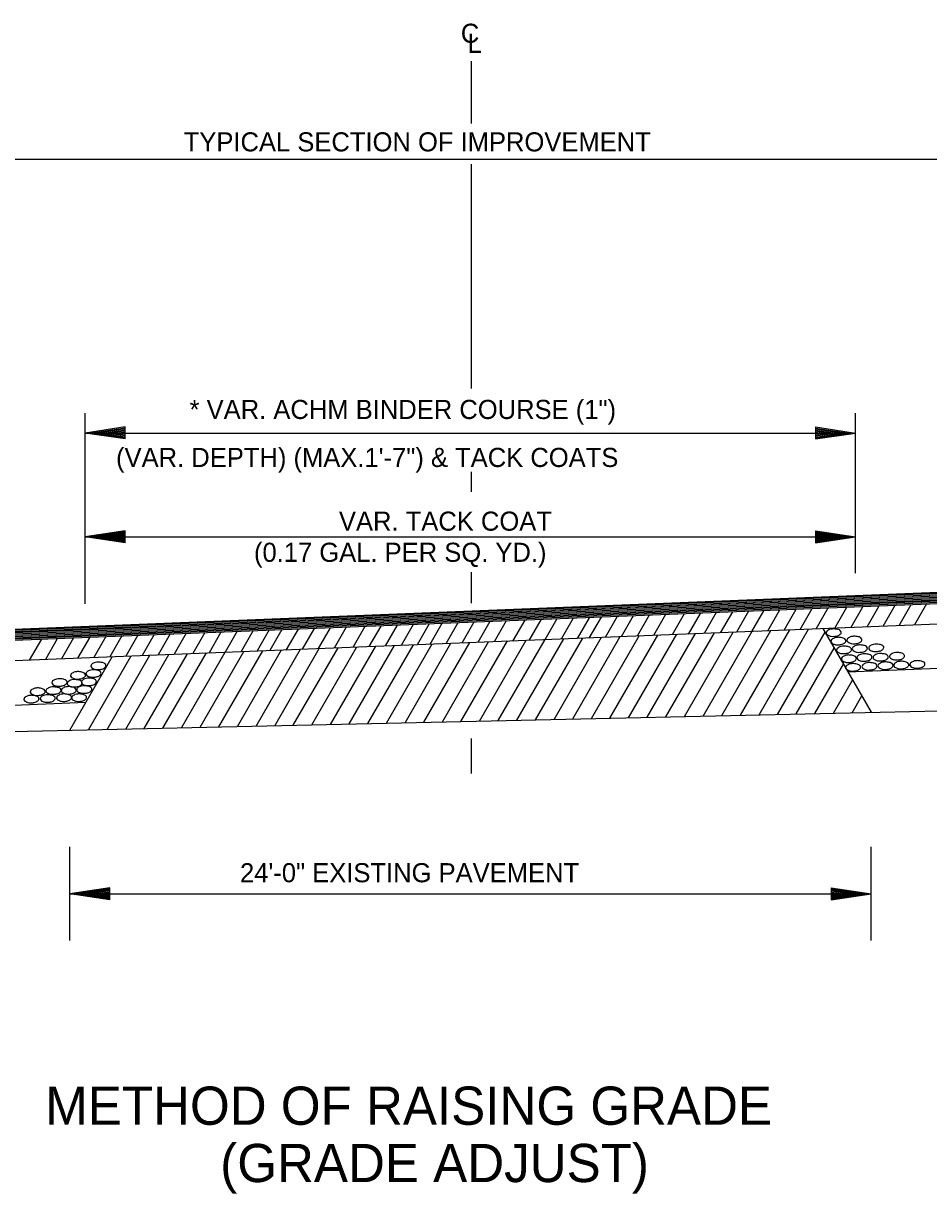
# Model space of a CAD drawing. Extents: x -2842 to 2681, y -2139 to 474.
# Drawn here: x 1630.4 to 1914.6, y -130.7 to 236.8 of the extents above; entities that cross this region are included whole.
import ezdxf

# ---------------------------------------------------------------- set-up
doc = ezdxf.new("R2010")
doc.units = 0
doc.layers.add('R_Grid', color=7, linetype='Continuous')

msp = doc.modelspace()

# ---------------------------------------------------------------- linework, layer by layer
at = {"layer": 'R_Grid'}
for p, q in [((1771.14, 205.36), (1771.14, 224.85)), ((1450.73, 194.15), (2091.8, 194.15)), ((1771.14, 129.55), (1771.14, 192.5)), ((1771.14, 122.12), (1771.14, 129.55)), ((1649.84, 54.48), (1649.84, 114.32)), ((1891.67, 64.06), (1891.67, 114.32)), ((1662.4, 110.03), (1649.84, 108.12)), ((1649.84, 108.12), (1891.67, 108.12)), ((1662.4, 106.24), (1649.84, 108.12)), ((1662.4, 109.69), (1651.92, 108.12)), ((1662.4, 106.55), (1651.92, 108.12)), ((1662.4, 109.42), (1654.08, 108.12)), ((1662.4, 106.85), (1654.08, 108.12)), ((1662.4, 109.06), (1656.19, 108.12)), ((1662.4, 107.19), (1656.19, 108.12)), ((1662.4, 108.76), (1658.31, 108.12)), ((1662.4, 107.49), (1658.31, 108.12)), ((1662.4, 108.42), (1660.42, 108.12)), ((1662.4, 107.84), (1660.42, 108.12)), ((1662.4, 106.24), (1662.4, 110.03)), ((1879.1, 110.03), (1891.67, 108.12)), ((1879.1, 110.03), (1879.1, 106.24)), ((1879.1, 109.69), (1889.56, 108.12)), ((1879.1, 109.42), (1887.39, 108.12)), ((1879.1, 109.06), (1885.28, 108.12)), ((1879.1, 108.76), (1883.15, 108.12)), ((1879.1, 108.42), (1881.09, 108.12)), ((1879.1, 106.24), (1891.67, 108.12)), ((1879.1, 107.49), (1883.15, 108.12)), ((1879.1, 106.85), (1887.39, 108.12)), ((1879.1, 106.55), (1889.56, 108.12)), ((1879.1, 107.19), (1885.28, 108.12)), ((1879.1, 107.84), (1881.09, 108.12)), ((1771.14, 89.65), (1771.14, 95.96)), ((1662.4, 77.41), (1649.84, 75.54)), ((1662.4, 73.64), (1662.4, 77.41)), ((1879.1, 77.41), (1891.67, 75.54)), ((1879.1, 77.41), (1879.1, 73.64)), ((1649.84, 75.54), (1891.67, 75.54)), ((1662.4, 73.64), (1649.84, 75.54)), ((1662.4, 77.12), (1651.92, 75.54)), ((1662.4, 73.98), (1651.92, 75.54)), ((1662.4, 76.79), (1654.08, 75.54)), ((1662.4, 74.28), (1654.08, 75.54)), ((1662.4, 76.5), (1656.19, 75.54)), ((1662.4, 74.61), (1656.19, 75.54)), ((1662.4, 76.13), (1658.31, 75.54)), ((1662.4, 74.92), (1658.31, 75.54)), ((1662.4, 75.85), (1660.42, 75.54)), ((1662.4, 75.25), (1660.42, 75.54)), ((1879.1, 77.12), (1889.56, 75.54)), ((1879.1, 76.79), (1887.39, 75.54)), ((1879.1, 76.5), (1885.28, 75.54)), ((1879.1, 76.13), (1883.15, 75.54)), ((1879.1, 75.85), (1881.09, 75.54)), ((1879.1, 73.64), (1891.67, 75.54)), ((1879.1, 74.92), (1883.15, 75.54)), ((1879.1, 74.28), (1887.39, 75.54)), ((1879.1, 73.98), (1889.56, 75.54)), ((1879.1, 74.61), (1885.28, 75.54)), ((1879.1, 75.25), (1881.09, 75.54)), ((1447.46, 37.85), (2094.71, 63.67)), ((1448.3, 38.28), (2093.98, 64.03)), ((1449.13, 38.68), (2093.27, 64.39)), ((1449.98, 39.13), (2092.52, 64.76)), ((1450.73, 39.48), (2091.83, 65.1)), ((1771.14, 54.66), (1771.14, 64.38)), ((1546.01, 40.97), (1996.02, 58.89)), ((1546.28, 41.37), (1995.73, 59.31)), ((1545.25, 39.8), (1996.79, 57.76)), ((1545.53, 40.17), (1996.53, 58.15)), ((1545.77, 40.58), (1996.27, 58.53)), ((1541.13, 33.2), (2001.08, 51.5)), ((1847.96, 51.75), (1844.19, 45.17)), ((1853.02, 51.95), (1849.24, 45.37)), ((1858.07, 52.13), (1854.29, 45.6)), ((1862.81, 52.29), (1859.03, 45.75)), ((1867.88, 52.53), (1864.08, 45.92)), ((1872.92, 52.71), (1869.15, 46.14)), ((1877.97, 52.9), (1874.19, 46.35)), ((1882.99, 53.13), (1879.24, 46.55)), ((1888.88, 53.36), (1885.08, 46.77)), ((1893.91, 53.45), (1890.18, 47)), ((1899.01, 53.76), (1895.22, 47.18)), ((1904.06, 53.97), (1900.29, 47.39)), ((1909.1, 54.15), (1905.33, 47.59)), ((1914.01, 54.44), (1910.25, 47.84)), ((1747.76, 47.8), (1743.96, 41.26)), ((1752.8, 48.01), (1749.03, 41.42)), ((1757.86, 48.21), (1754.07, 41.63)), ((1761.76, 48.29), (1757.99, 41.72)), ((1766.83, 48.47), (1763.04, 41.93)), ((1771.87, 48.68), (1768.09, 42.1)), ((1776.91, 48.91), (1773.15, 42.31)), ((1781.98, 49.1), (1778.22, 42.54)), ((1787.83, 49.31), (1784.03, 42.74)), ((1792.86, 49.42), (1789.14, 42.95)), ((1797.94, 49.74), (1794.19, 43.15)), ((1803.02, 49.92), (1799.23, 43.39)), ((1808.06, 50.12), (1804.29, 43.56)), ((1811.78, 50.31), (1807.99, 43.72)), ((1816.86, 50.52), (1813.05, 43.92)), ((1821.88, 50.68), (1818.12, 44.16)), ((1826.93, 50.89), (1823.16, 44.33)), ((1831.99, 51.13), (1828.22, 44.52)), ((1837.86, 51.32), (1834.08, 44.77)), ((1842.88, 51.42), (1839.15, 44.98)), ((1656.28, 44.2), (1652.5, 37.65)), ((1661.32, 44.43), (1657.53, 37.86)), ((1666.39, 44.63), (1662.62, 38.07)), ((1671.43, 44.88), (1667.66, 38.29)), ((1676.49, 45.05), (1672.73, 38.48)), ((1681.52, 45.25), (1677.76, 38.67)), ((1687.38, 45.5), (1683.61, 38.91)), ((1692.42, 45.6), (1688.69, 39.13)), ((1697.5, 45.88), (1693.74, 39.31)), ((1702.57, 46.09), (1698.8, 39.52)), ((1707.6, 46.31), (1703.84, 39.75)), ((1711.54, 46.36), (1707.77, 39.81)), ((1716.65, 46.56), (1712.85, 39.97)), ((1721.66, 46.75), (1717.89, 40.19)), ((1726.73, 46.97), (1722.95, 40.4)), ((1731.76, 47.17), (1728, 40.6)), ((1737.6, 47.4), (1733.82, 40.81)), ((1742.63, 47.5), (1738.91, 41.04)), ((1802.9, 18.32), (1817.85, 44.21)), ((1808.75, 18.45), (1823.76, 44.44)), ((1814.6, 18.58), (1829.67, 44.68)), ((1820.45, 18.71), (1835.58, 44.91)), ((1826.3, 18.84), (1841.49, 45.15)), ((1832.15, 18.98), (1847.4, 45.38)), ((1838, 19.11), (1853.31, 45.62)), ((1843.85, 19.24), (1859.22, 45.86)), ((1849.7, 19.37), (1865.13, 46.09)), ((1855.55, 19.5), (1871.04, 46.33)), ((1861.4, 19.63), (1876.94, 46.56)), ((1867.25, 19.76), (1882.15, 45.57)), ((1881.47, 46.74), (1896.62, 20.43)), ((1636.05, 43.4), (1632.26, 36.81)), ((1641.05, 43.49), (1637.33, 37.02)), ((1646.15, 43.77), (1642.38, 37.22)), ((1651.23, 43.99), (1647.44, 37.43)), ((1709.31, 16.21), (1723.3, 40.45)), ((1715.16, 16.34), (1729.21, 40.68)), ((1721.01, 16.48), (1735.12, 40.92)), ((1726.86, 16.61), (1741.03, 41.15)), ((1732.71, 16.74), (1746.94, 41.39)), ((1738.56, 16.87), (1752.85, 41.62)), ((1744.41, 17), (1758.76, 41.86)), ((1750.26, 17.13), (1764.67, 42.09)), ((1756.11, 17.27), (1770.58, 42.33)), ((1761.96, 17.4), (1776.49, 42.56)), ((1767.81, 17.53), (1782.4, 42.8)), ((1773.66, 17.66), (1788.31, 43.03)), ((1779.51, 17.79), (1794.21, 43.27)), ((1785.36, 17.92), (1800.12, 43.5)), ((1791.2, 18.05), (1806.03, 43.74)), ((1797.05, 18.19), (1811.94, 43.97)), ((1873.1, 19.9), (1885.03, 40.56)), ((1644.97, 14.77), (1658.27, 37.86)), ((1644.97, 14.77), (1658.3, 37.86)), ((1650.82, 14.9), (1664.21, 38.09)), ((1656.67, 15.03), (1670.12, 38.33)), ((1662.52, 15.16), (1676.03, 38.56)), ((1668.37, 15.29), (1681.94, 38.8)), ((1674.22, 15.42), (1687.85, 39.04)), ((1680.06, 15.55), (1693.76, 39.27)), ((1685.91, 15.69), (1699.67, 39.51)), ((1691.76, 15.82), (1705.58, 39.74)), ((1697.61, 15.95), (1711.48, 39.98)), ((1703.46, 16.08), (1717.39, 40.21)), ((1889.32, 33.11), (2010.36, 37.94)), ((1878.95, 20.03), (1887.91, 35.56)), ((1884.8, 20.16), (1890.79, 30.55)), ((1398.89, 13.57), (1650.04, 23.58)), ((1890.65, 20.29), (1893.68, 25.54)), ((1594.52, 13.63), (1946.93, 21.56)), ((1896.49, 20.42), (1896.56, 20.54)), ((1771.14, 1.22), (1771.14, 12.2)), ((1644.97, -51.3), (1644.97, -21.87)), ((1896.62, -51.3), (1896.62, -21.87)), ((1657.55, -34.75), (1644.97, -36.64)), ((1644.97, -36.64), (1896.62, -36.64)), ((1657.55, -38.52), (1644.97, -36.64)), ((1657.55, -35.05), (1647.06, -36.64)), ((1657.55, -38.19), (1647.06, -36.64)), ((1657.55, -35.39), (1649.25, -36.64)), ((1657.55, -37.88), (1649.25, -36.64)), ((1657.55, -35.67), (1651.32, -36.64)), ((1657.55, -37.57), (1651.32, -36.64)), ((1657.55, -36.03), (1653.47, -36.64)), ((1657.55, -37.25), (1653.47, -36.64)), ((1657.55, -36.31), (1655.56, -36.64)), ((1657.55, -36.92), (1655.56, -36.64)), ((1657.55, -38.52), (1657.55, -34.75)), ((1884.05, -34.75), (1896.62, -36.64)), ((1884.05, -34.75), (1884.05, -38.52)), ((1884.05, -35.05), (1894.5, -36.64)), ((1884.05, -35.39), (1892.35, -36.64)), ((1884.05, -35.67), (1890.27, -36.64)), ((1884.05, -36.03), (1888.14, -36.64)), ((1884.05, -36.31), (1886.01, -36.64)), ((1884.05, -38.52), (1896.62, -36.64)), ((1884.05, -37.25), (1888.14, -36.64)), ((1884.05, -37.88), (1892.35, -36.64)), ((1884.05, -38.19), (1894.5, -36.64)), ((1884.05, -37.57), (1890.27, -36.64)), ((1884.05, -36.92), (1886.01, -36.64))]:
    msp.add_line(p, q, dxfattribs=at)
for points in [[(1884.85, 44.27), (1884.01, 44.28), (1883.1, 44.61), (1882.56, 45.06), (1882.51, 45.32), (1882.72, 45.88), (1883.04, 46.11), (1883.57, 46.38), (1884.39, 46.56), (1884.78, 46.6), (1885.42, 46.55), (1886.1, 46.44), (1886.64, 46.26), (1887.14, 45.83), (1887.23, 45.54), (1887.08, 45.08), (1886.7, 44.74), (1886.32, 44.5), (1885.75, 44.36), (1885.38, 44.28), (1884.85, 44.27)], [(1891.32, 41.96), (1890.48, 41.97), (1889.57, 42.3), (1889.03, 42.75), (1888.98, 43.01), (1889.2, 43.56), (1889.51, 43.8), (1890.05, 44.07), (1890.86, 44.25), (1891.25, 44.29), (1891.89, 44.24), (1892.58, 44.13), (1893.11, 43.95), (1893.61, 43.52), (1893.7, 43.23), (1893.56, 42.76), (1893.18, 42.42), (1892.8, 42.19), (1892.22, 42.05), (1891.86, 41.97), (1891.32, 41.96)], [(1886.3, 41.63), (1885.46, 41.64), (1884.55, 41.96), (1884.01, 42.42), (1883.96, 42.68), (1884.18, 43.23), (1884.49, 43.47), (1885.03, 43.74), (1885.84, 43.92), (1886.23, 43.96), (1886.87, 43.91), (1887.56, 43.8), (1888.09, 43.61), (1888.59, 43.19), (1888.68, 42.9), (1888.54, 42.43), (1888.16, 42.09), (1887.78, 41.86), (1887.2, 41.72), (1886.84, 41.64), (1886.3, 41.63)], [(1888.09, 38.85), (1887.25, 38.87), (1886.33, 39.19), (1885.8, 39.64), (1885.74, 39.9), (1885.96, 40.46), (1886.28, 40.7), (1886.81, 40.96), (1887.63, 41.15), (1888.01, 41.19), (1888.65, 41.13), (1889.34, 41.03), (1889.87, 40.84), (1890.38, 40.41), (1890.47, 40.13), (1890.32, 39.66), (1889.94, 39.32), (1889.56, 39.09), (1888.98, 38.95), (1888.62, 38.87), (1888.09, 38.85)], [(1893.04, 39.25), (1892.2, 39.26), (1891.29, 39.59), (1890.75, 40.04), (1890.69, 40.3), (1890.91, 40.86), (1891.23, 41.09), (1891.76, 41.36), (1892.58, 41.54), (1892.97, 41.59), (1893.61, 41.53), (1894.29, 41.42), (1894.83, 41.24), (1895.33, 40.81), (1895.42, 40.53), (1895.27, 40.06), (1894.89, 39.72), (1894.51, 39.48), (1893.94, 39.34), (1893.57, 39.26), (1893.04, 39.25)], [(1898.19, 39.51), (1897.35, 39.53), (1896.44, 39.85), (1895.9, 40.3), (1895.85, 40.56), (1896.06, 41.12), (1896.38, 41.36), (1896.91, 41.62), (1897.73, 41.81), (1898.12, 41.85), (1898.76, 41.79), (1899.45, 41.69), (1899.98, 41.5), (1900.48, 41.07), (1900.57, 40.79), (1900.42, 40.32), (1900.04, 39.98), (1899.66, 39.75), (1899.09, 39.61), (1898.73, 39.53), (1898.19, 39.51)], [(1889.61, 36.08), (1888.76, 36.09), (1887.85, 36.42), (1887.32, 36.87), (1887.26, 37.13), (1887.48, 37.69), (1887.79, 37.92), (1888.33, 38.19), (1889.15, 38.37), (1889.53, 38.41), (1890.17, 38.36), (1890.86, 38.25), (1891.39, 38.07), (1891.9, 37.64), (1891.98, 37.36), (1891.84, 36.89), (1891.46, 36.55), (1891.08, 36.31), (1890.5, 36.17), (1890.14, 36.09), (1889.61, 36.08)], [(1894.49, 36.47), (1893.65, 36.49), (1892.74, 36.81), (1892.2, 37.27), (1892.15, 37.53), (1892.37, 38.08), (1892.68, 38.32), (1893.22, 38.58), (1894.03, 38.77), (1894.42, 38.81), (1895.06, 38.75), (1895.75, 38.65), (1896.28, 38.46), (1896.78, 38.03), (1896.87, 37.75), (1896.73, 37.28), (1896.35, 36.94), (1895.97, 36.71), (1895.39, 36.57), (1895.03, 36.49), (1894.49, 36.47)], [(1899.58, 36.54), (1898.74, 36.56), (1897.82, 36.88), (1897.29, 37.33), (1897.23, 37.59), (1897.45, 38.15), (1897.77, 38.38), (1898.3, 38.65), (1899.12, 38.84), (1899.51, 38.88), (1900.14, 38.82), (1900.83, 38.72), (1901.37, 38.53), (1901.87, 38.1), (1901.96, 37.82), (1901.81, 37.35), (1901.43, 37.01), (1901.05, 36.77), (1900.48, 36.64), (1900.11, 36.56), (1899.58, 36.54)], [(1904.73, 36.87), (1903.89, 36.89), (1902.97, 37.21), (1902.44, 37.66), (1902.38, 37.92), (1902.6, 38.48), (1902.92, 38.71), (1903.45, 38.98), (1904.27, 39.17), (1904.66, 39.21), (1905.3, 39.15), (1905.98, 39.05), (1906.52, 38.86), (1907.02, 38.43), (1907.11, 38.15), (1906.96, 37.68), (1906.58, 37.34), (1906.2, 37.1), (1905.63, 36.97), (1905.26, 36.89), (1904.73, 36.87)], [(1647.53, 30.85), (1646.69, 30.87), (1645.78, 31.19), (1645.25, 31.65), (1645.19, 31.91), (1645.41, 32.46), (1645.72, 32.7), (1646.26, 32.97), (1647.07, 33.15), (1647.46, 33.19), (1648.1, 33.14), (1648.79, 33.03), (1649.32, 32.84), (1649.82, 32.42), (1649.91, 32.13), (1649.77, 31.66), (1649.39, 31.32), (1649.01, 31.09), (1648.43, 30.95), (1648.07, 30.87), (1647.53, 30.85)], [(1652.41, 31.45), (1651.57, 31.47), (1650.65, 31.79), (1650.12, 32.25), (1650.06, 32.5), (1650.28, 33.06), (1650.6, 33.3), (1651.13, 33.56), (1651.95, 33.75), (1652.34, 33.79), (1652.98, 33.73), (1653.66, 33.63), (1654.2, 33.44), (1654.7, 33.01), (1654.79, 32.73), (1654.64, 32.26), (1654.26, 31.92), (1653.88, 31.69), (1653.31, 31.55), (1652.94, 31.47), (1652.41, 31.45)], [(1653.95, 33.85), (1653.11, 33.86), (1652.19, 34.19), (1651.66, 34.64), (1651.6, 34.9), (1651.82, 35.46), (1652.14, 35.69), (1652.67, 35.96), (1653.49, 36.14), (1653.88, 36.19), (1654.52, 36.13), (1655.2, 36.02), (1655.74, 35.84), (1656.24, 35.41), (1656.33, 35.13), (1656.18, 34.66), (1655.8, 34.32), (1655.42, 34.08), (1654.85, 33.94), (1654.48, 33.86), (1653.95, 33.85)], [(1890.93, 33.37), (1890.09, 33.39), (1889.17, 33.71), (1888.64, 34.16), (1888.58, 34.42), (1888.8, 34.98), (1889.12, 35.21), (1889.65, 35.48), (1890.47, 35.67), (1890.85, 35.71), (1891.49, 35.65), (1892.18, 35.55), (1892.71, 35.36), (1893.22, 34.93), (1893.3, 34.65), (1893.16, 34.18), (1892.78, 33.84), (1892.4, 33.6), (1891.82, 33.47), (1891.46, 33.39), (1890.93, 33.37)], [(1896.08, 33.7), (1895.24, 33.72), (1894.32, 34.04), (1893.79, 34.49), (1893.73, 34.75), (1893.95, 35.31), (1894.27, 35.54), (1894.8, 35.81), (1895.62, 36), (1896.01, 36.04), (1896.64, 35.98), (1897.33, 35.88), (1897.87, 35.69), (1898.37, 35.26), (1898.46, 34.98), (1898.31, 34.51), (1897.93, 34.17), (1897.55, 33.93), (1896.98, 33.8), (1896.61, 33.72), (1896.08, 33.7)], [(1901.1, 33.9), (1900.26, 33.91), (1899.34, 34.24), (1898.81, 34.69), (1898.75, 34.95), (1898.97, 35.51), (1899.29, 35.74), (1899.82, 36.01), (1900.64, 36.2), (1901.02, 36.24), (1901.66, 36.18), (1902.35, 36.07), (1902.89, 35.89), (1903.39, 35.46), (1903.48, 35.18), (1903.33, 34.71), (1902.95, 34.37), (1902.57, 34.13), (1902, 34), (1901.63, 33.91), (1901.1, 33.9)], [(1906.05, 34.1), (1905.21, 34.11), (1904.3, 34.44), (1903.76, 34.89), (1903.71, 35.15), (1903.92, 35.71), (1904.24, 35.94), (1904.77, 36.21), (1905.59, 36.39), (1905.98, 36.43), (1906.62, 36.38), (1907.3, 36.27), (1907.84, 36.09), (1908.34, 35.66), (1908.43, 35.37), (1908.28, 34.9), (1907.9, 34.57), (1907.52, 34.33), (1906.95, 34.19), (1906.58, 34.11), (1906.05, 34.1)], [(1911.14, 34.29), (1910.3, 34.31), (1909.38, 34.63), (1908.85, 35.09), (1908.79, 35.35), (1909.01, 35.9), (1909.32, 36.14), (1909.86, 36.41), (1910.68, 36.59), (1911.06, 36.63), (1911.7, 36.58), (1912.39, 36.47), (1912.92, 36.28), (1913.43, 35.86), (1913.51, 35.57), (1913.37, 35.1), (1912.99, 34.76), (1912.61, 34.53), (1912.03, 34.39), (1911.67, 34.31), (1911.14, 34.29)], [(1641.72, 28.63), (1640.88, 28.65), (1639.96, 28.97), (1639.43, 29.42), (1639.37, 29.68), (1639.59, 30.24), (1639.91, 30.47), (1640.44, 30.74), (1641.26, 30.93), (1641.65, 30.97), (1642.29, 30.91), (1642.97, 30.81), (1643.51, 30.62), (1644.01, 30.19), (1644.1, 29.91), (1643.95, 29.44), (1643.57, 29.1), (1643.19, 28.87), (1642.62, 28.73), (1642.25, 28.65), (1641.72, 28.63)], [(1646.51, 28.37), (1645.67, 28.39), (1644.75, 28.71), (1644.22, 29.17), (1644.16, 29.43), (1644.38, 29.98), (1644.7, 30.22), (1645.23, 30.49), (1646.05, 30.67), (1646.44, 30.71), (1647.07, 30.65), (1647.76, 30.55), (1648.3, 30.36), (1648.8, 29.94), (1648.89, 29.65), (1648.74, 29.18), (1648.36, 28.84), (1647.98, 28.61), (1647.41, 28.47), (1647.04, 28.39), (1646.51, 28.37)], [(1650.96, 28.8), (1650.11, 28.82), (1649.2, 29.14), (1648.67, 29.59), (1648.61, 29.85), (1648.83, 30.41), (1649.14, 30.65), (1649.68, 30.91), (1650.49, 31.1), (1650.88, 31.14), (1651.52, 31.08), (1652.21, 30.98), (1652.74, 30.79), (1653.24, 30.36), (1653.33, 30.08), (1653.19, 29.61), (1652.81, 29.27), (1652.43, 29.04), (1651.85, 28.9), (1651.49, 28.82), (1650.96, 28.8)], [(1632.91, 23.41), (1632.07, 23.43), (1631.15, 23.75), (1630.62, 24.21), (1630.56, 24.46), (1630.78, 25.02), (1631.1, 25.26), (1631.63, 25.52), (1632.45, 25.71), (1632.84, 25.75), (1633.48, 25.69), (1634.16, 25.59), (1634.7, 25.4), (1635.2, 24.97), (1635.29, 24.69), (1635.14, 24.22), (1634.76, 23.88), (1634.38, 23.65), (1633.81, 23.51), (1633.44, 23.43), (1632.91, 23.41)], [(1634.88, 25.72), (1634.04, 25.74), (1633.12, 26.06), (1632.59, 26.52), (1632.53, 26.77), (1632.75, 27.33), (1633.06, 27.57), (1633.6, 27.83), (1634.42, 28.02), (1634.8, 28.06), (1635.44, 28), (1636.13, 27.9), (1636.66, 27.71), (1637.17, 27.28), (1637.25, 27), (1637.11, 26.53), (1636.73, 26.19), (1636.35, 25.96), (1635.77, 25.82), (1635.41, 25.74), (1634.88, 25.72)], [(1638.04, 23.58), (1637.2, 23.6), (1636.29, 23.92), (1635.75, 24.38), (1635.7, 24.64), (1635.91, 25.19), (1636.23, 25.43), (1636.76, 25.7), (1637.58, 25.88), (1637.97, 25.92), (1638.61, 25.87), (1639.29, 25.76), (1639.83, 25.57), (1640.33, 25.15), (1640.42, 24.86), (1640.27, 24.39), (1639.89, 24.05), (1639.51, 23.82), (1638.94, 23.68), (1638.58, 23.6), (1638.04, 23.58)], [(1639.84, 26.06), (1639, 26.08), (1638.08, 26.4), (1637.55, 26.86), (1637.49, 27.12), (1637.71, 27.67), (1638.03, 27.91), (1638.56, 28.18), (1639.38, 28.36), (1639.76, 28.4), (1640.4, 28.35), (1641.09, 28.24), (1641.62, 28.05), (1642.13, 27.63), (1642.22, 27.34), (1642.07, 26.87), (1641.69, 26.53), (1641.31, 26.3), (1640.74, 26.16), (1640.37, 26.08), (1639.84, 26.06)], [(1643.17, 23.84), (1642.33, 23.86), (1641.42, 24.18), (1640.88, 24.63), (1640.83, 24.89), (1641.05, 25.45), (1641.36, 25.69), (1641.89, 25.95), (1642.71, 26.14), (1643.1, 26.18), (1643.74, 26.12), (1644.43, 26.02), (1644.96, 25.83), (1645.46, 25.4), (1645.55, 25.12), (1645.41, 24.65), (1645.03, 24.31), (1644.64, 24.08), (1644.07, 23.94), (1643.71, 23.86), (1643.17, 23.84)], [(1644.63, 26.15), (1643.79, 26.17), (1642.87, 26.49), (1642.34, 26.94), (1642.28, 27.2), (1642.5, 27.76), (1642.82, 27.99), (1643.35, 28.26), (1644.17, 28.45), (1644.55, 28.49), (1645.19, 28.43), (1645.88, 28.33), (1646.41, 28.14), (1646.92, 27.71), (1647, 27.43), (1646.86, 26.96), (1646.48, 26.62), (1646.1, 26.38), (1645.52, 26.25), (1645.16, 26.17), (1644.63, 26.15)], [(1647.88, 23.84), (1647.04, 23.86), (1646.12, 24.18), (1645.59, 24.63), (1645.53, 24.89), (1645.75, 25.45), (1646.07, 25.69), (1646.6, 25.95), (1647.42, 26.14), (1647.8, 26.18), (1648.44, 26.12), (1649.13, 26.02), (1649.66, 25.83), (1650.17, 25.4), (1650.25, 25.12), (1650.11, 24.65), (1649.73, 24.31), (1649.35, 24.08), (1648.77, 23.94), (1648.41, 23.86), (1647.88, 23.84)], [(1649.5, 26.41), (1648.66, 26.42), (1647.75, 26.75), (1647.21, 27.2), (1647.16, 27.46), (1647.37, 28.02), (1647.69, 28.25), (1648.22, 28.52), (1649.04, 28.7), (1649.43, 28.74), (1650.07, 28.69), (1650.76, 28.58), (1651.29, 28.4), (1651.79, 27.97), (1651.88, 27.68), (1651.73, 27.22), (1651.35, 26.88), (1650.97, 26.64), (1650.4, 26.5), (1650.04, 26.42), (1649.5, 26.41)]]:
    msp.add_spline(points, degree=3, dxfattribs=at)

# ---------------------------------------------------------------- texts
for s, height, p in [('C', 6, (1767.76, 230.66)), ('L', 6, (1769.91, 227.5)), ('TYPICAL SECTION OF IMPROVEMENT', 6, (1680.75, 196.55)), ('* VAR. ACHM BINDER COURSE (1")', 6, (1682.59, 112.52)), ('(VAR. DEPTH) (MAX.1\'-7") & TACK COATS', 6, (1659.5, 97.45)), ('VAR. TACK COAT', 6, (1729.49, 77.44)), ('(0.17 GAL. PER SQ. YD.)', 6, (1702.81, 67.66)), ('24\'-0" EXISTING PAVEMENT', 6, (1698.43, -32.97)), ('METHOD OF RAISING GRADE', 12, (1637.25, -109.13)), ('(GRADE ADJUST)', 12, (1692.21, -127.13))]:
    msp.add_text(s, height=height, dxfattribs=at).set_placement(p)

doc.saveas('drawing.dxf')
